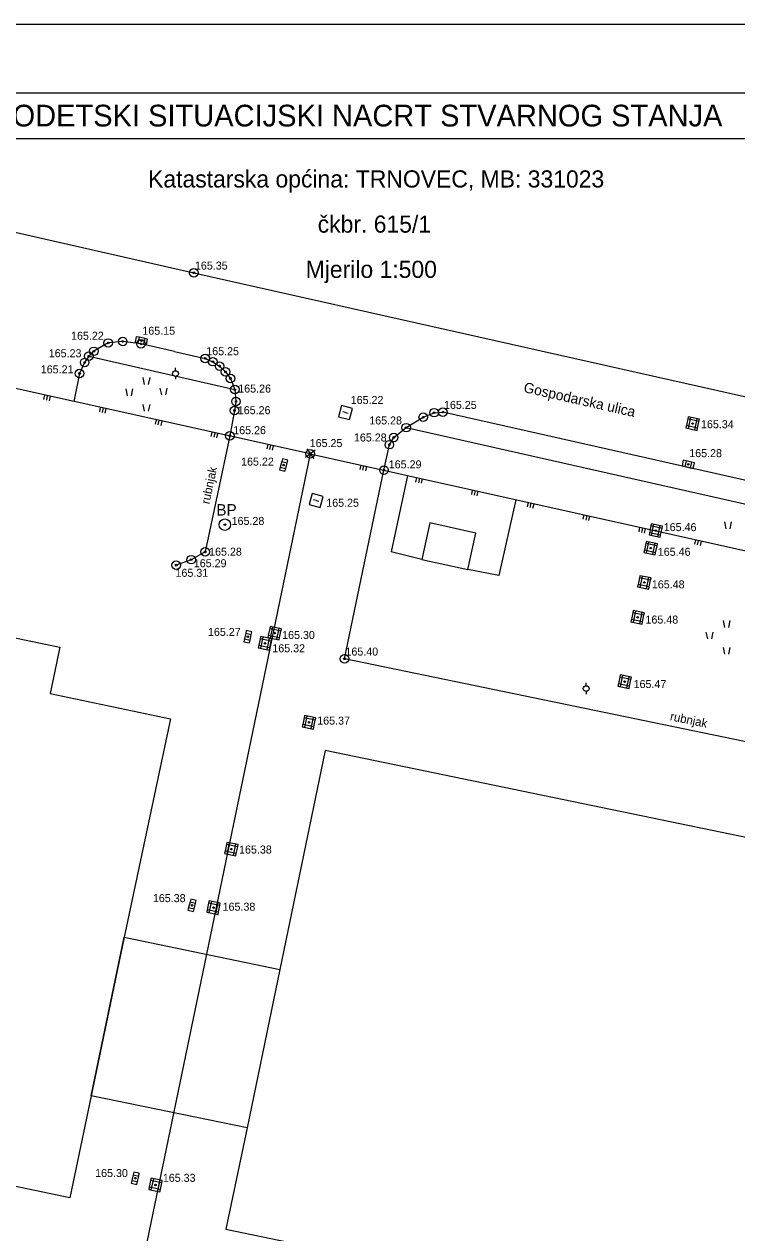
# Model space of a CAD drawing. Extents: x 492698 to 492905, y 5129124 to 5129334.
# Drawn here: x 492792.6 to 492855, y 5129228 to 5129333.7 of the extents above; entities that cross this region are included whole.
import ezdxf

# ---------------------------------------------------------------- set-up
doc = ezdxf.new("R2010")
doc.units = 0
for name, color, linetype in [('DETALJNE TOČKE', 7, 'Continuous'), ('KUĆNI BROJ', 7, 'Continuous'), ('MEĐA - stara', 7, 'Continuous'), ('MEĐAŠI', 7, 'Continuous'), ('NAZIVI POSJEDNIKA', 7, 'Continuous'), ('OBJEKTI - novi', 7, 'Continuous'), ('OBJEKTI - stari', 7, 'Continuous'), ('OBRAZCI', 7, 'Continuous'), ('TOPO - Znakovi', 7, 'Continuous'), ('VISINE', 7, 'Continuous')]:
    doc.layers.add(name, color=color, linetype=linetype)

msp = doc.modelspace()

# ---------------------------------------------------------------- linework, layer by layer
at = {"layer": 'MEĐA - stara'}
for p, q in [((492762.85, 5129322.07), (492807.48, 5129311.96)), ((492807.48, 5129311.96), (492891.56, 5129293.06)), ((492817.66, 5129296.12), (492756.96, 5129309.58)), ((492799.98, 5129305.82), (492798.72, 5129305.09)), ((492801.25, 5129305.95), (492799.98, 5129305.82)), ((492802.85, 5129305.74), (492801.25, 5129305.95)), ((492805.79, 5129305.06), (492802.85, 5129305.74)), ((492797.92, 5129304.1), (492797.47, 5129303.15)), ((492798.29, 5129304.66), (492797.92, 5129304.1)), ((492798.72, 5129305.09), (492798.29, 5129304.66)), ((492798.29, 5129304.66), (492811.06, 5129301.74)), ((492805.79, 5129305.06), (492808.47, 5129304.47)), ((492808.47, 5129304.47), (492809.14, 5129304.18)), ((492809.14, 5129304.18), (492809.73, 5129303.79)), ((492797.47, 5129303.15), (492796.97, 5129300.71)), ((492809.73, 5129303.79), (492810.25, 5129303.29)), ((492810.25, 5129303.29), (492810.68, 5129302.71)), ((492803.01, 5129302.8), (492803.13, 5129302.2)), ((492803.61, 5129302.8), (492803.48, 5129302.2)), ((492810.68, 5129302.71), (492811.06, 5129301.74)), ((492801.51, 5129301.8), (492801.63, 5129301.2)), ((492802.11, 5129301.8), (492801.98, 5129301.2)), ((492804.51, 5129301.87), (492804.63, 5129301.27)), ((492805.11, 5129301.87), (492804.98, 5129301.27)), ((492811.06, 5129301.74), (492811.16, 5129300.7)), ((492803.01, 5129300.45), (492803.13, 5129299.85)), ((492803.61, 5129300.45), (492803.48, 5129299.85)), ((492811.04, 5129299.91), (492810.62, 5129297.7)), ((492811.16, 5129300.7), (492811.04, 5129299.91)), ((492826.05, 5129298.41), (492827.55, 5129299.32)), ((492827.55, 5129299.32), (492828.5, 5129299.72)), ((492828.5, 5129299.72), (492829.27, 5129299.77)), ((492873.79, 5129289.71), (492829.27, 5129299.77)), ((492824.96, 5129297.55), (492826.05, 5129298.41)), ((492826.05, 5129298.41), (492875.78, 5129287.23)), ((492810.62, 5129297.7), (492808.47, 5129287.54)), ((492824.11, 5129294.7), (492824.58, 5129296.92)), ((492824.58, 5129296.92), (492824.96, 5129297.55)), ((492817.66, 5129296.12), (492788.55, 5129155.62)), ((492817.66, 5129296.12), (492882.48, 5129281.67)), ((492820.65, 5129278.19), (492824.11, 5129294.7)), ((492826.18, 5129294.22), (492824.75, 5129287.55)), ((492835.65, 5129292.11), (492834.15, 5129285.48)), ((492853.9, 5129290.17), (492854.03, 5129289.57)), ((492854.5, 5129290.17), (492854.38, 5129289.57)), ((492808.47, 5129287.54), (492807.24, 5129286.86)), ((492827.43, 5129286.89), (492824.75, 5129287.55)), ((492807.24, 5129286.86), (492805.93, 5129286.38)), ((492834.15, 5129285.48), (492831.44, 5129286)), ((492853.78, 5129281.53), (492853.91, 5129280.93)), ((492854.38, 5129281.53), (492854.26, 5129280.93)), ((492852.28, 5129280.53), (492852.41, 5129279.93)), ((492852.88, 5129280.53), (492852.76, 5129279.93)), ((492853.78, 5129279.18), (492853.91, 5129278.58)), ((492854.38, 5129279.18), (492854.26, 5129278.58)), ((492872.52, 5129267.46), (492820.65, 5129278.19))]:
    msp.add_line(p, q, dxfattribs=at)
at = {"layer": 'MEĐAŠI'}
for p, q in [((492818.09, 5129296.43), (492817.23, 5129295.81)), ((492817.35, 5129296.55), (492817.97, 5129295.69))]:
    msp.add_line(p, q, dxfattribs=at)
for centre, radius in [((492807.48, 5129311.96), 0.375), ((492807.48, 5129311.96), 0.075), ((492799.98, 5129305.82), 0.375), ((492801.25, 5129305.95), 0.375), ((492798.72, 5129305.09), 0.375), ((492798.72, 5129305.09), 0.075), ((492799.98, 5129305.82), 0.075), ((492801.25, 5129305.95), 0.075), ((492802.85, 5129305.74), 0.375), ((492802.85, 5129305.74), 0.075), ((492797.92, 5129304.1), 0.375), ((492797.92, 5129304.1), 0.075), ((492798.29, 5129304.66), 0.375), ((492798.29, 5129304.66), 0.075), ((492808.47, 5129304.47), 0.375), ((492808.47, 5129304.47), 0.075), ((492809.14, 5129304.18), 0.375), ((492809.14, 5129304.18), 0.075), ((492809.73, 5129303.79), 0.375), ((492797.47, 5129303.15), 0.375), ((492797.47, 5129303.15), 0.075), ((492809.73, 5129303.79), 0.075), ((492810.25, 5129303.29), 0.375), ((492810.25, 5129303.29), 0.075), ((492810.68, 5129302.71), 0.375), ((492810.68, 5129302.71), 0.075), ((492811.06, 5129301.74), 0.375), ((492811.16, 5129300.7), 0.375), ((492811.06, 5129301.74), 0.075), ((492811.04, 5129299.91), 0.375), ((492811.04, 5129299.91), 0.075), ((492811.16, 5129300.7), 0.075), ((492828.5, 5129299.72), 0.375), ((492829.27, 5129299.77), 0.375), ((492829.27, 5129299.77), 0.075), ((492826.05, 5129298.41), 0.375), ((492827.55, 5129299.32), 0.375), ((492827.55, 5129299.32), 0.075), ((492828.5, 5129299.72), 0.075), ((492810.62, 5129297.7), 0.375), ((492810.62, 5129297.7), 0.075), ((492824.96, 5129297.55), 0.375), ((492826.05, 5129298.41), 0.075), ((492824.58, 5129296.92), 0.375), ((492824.58, 5129296.92), 0.075), ((492824.96, 5129297.55), 0.075), ((492817.66, 5129296.12), 0.075), ((492824.11, 5129294.7), 0.375), ((492824.11, 5129294.7), 0.075), ((492807.24, 5129286.86), 0.375), ((492808.47, 5129287.54), 0.375), ((492808.47, 5129287.54), 0.075), ((492805.93, 5129286.38), 0.375), ((492805.93, 5129286.38), 0.075), ((492807.24, 5129286.86), 0.075), ((492820.65, 5129278.19), 0.375), ((492820.65, 5129278.19), 0.075)]:
    msp.add_circle(centre, radius, dxfattribs=at)
for start, end in [(170.9579, 350.9579), (350.9579, 170.9579)]:
    msp.add_arc((492817.66, 5129296.12), 0.075, start, end, dxfattribs=at)
at = {"layer": 'OBJEKTI - novi'}
msp.add_circle((492817.66, 5129296.12), 0.375, dxfattribs=at)
at = {"layer": 'OBJEKTI - stari'}
for points in [[(492828.11, 5129290.08), (492827.43, 5129286.89), (492831.44, 5129286), (492832.15, 5129289.18)], [(492805.42, 5129272.95), (492801.38, 5129253.83), (492798.48, 5129239.95), (492796.63, 5129231.02), (492786.16, 5129233.21), (492785.3, 5129229.11), (492772.8, 5129231.7), (492773.65, 5129235.81), (492723.64, 5129246.23), (492732.34, 5129288.11), (492782.39, 5129277.73), (492783.23, 5129281.79), (492795.74, 5129279.2), (492794.89, 5129275.14)], [(492818.96, 5129270.18), (492815.01, 5129251.01), (492812.14, 5129237.15), (492810.27, 5129228.29), (492862.15, 5129217.52), (492870.87, 5129259.44)], [(492801.38, 5129253.83), (492815.01, 5129251.01), (492812.14, 5129237.15), (492798.48, 5129239.95)]]:
    msp.add_lwpolyline(points, close=True, dxfattribs=at)
at = {"layer": 'OBRAZCI'}
for p, q in [((492748.91, 5129333.71), (492897.41, 5129333.71)), ((492754.91, 5129327.71), (492891.41, 5129327.71)), ((492754.91, 5129327.71), (492847.91, 5129327.71)), ((492754.91, 5129327.71), (492847.91, 5129327.71)), ((492754.91, 5129327.71), (492847.91, 5129327.71)), ((492754.91, 5129327.71), (492847.91, 5129327.71)), ((492754.91, 5129323.71), (492891.41, 5129323.71))]:
    msp.add_line(p, q, dxfattribs=at)
at = {"layer": 'TOPO - Znakovi'}
for p, q in [((492802.44, 5129306.37), (492802.34, 5129305.88)), ((492802.69, 5129306.32), (492802.44, 5129306.37)), ((492802.69, 5129306.32), (492802.58, 5129305.83)), ((492803.18, 5129306.21), (492802.69, 5129306.32)), ((492803.18, 5129306.21), (492803.07, 5129305.72)), ((492803.42, 5129306.16), (492803.18, 5129306.21)), ((492802.34, 5129305.88), (492802.58, 5129305.83)), ((492802.58, 5129305.83), (492803.07, 5129305.72)), ((492803.07, 5129305.72), (492803.32, 5129305.67)), ((492803.32, 5129305.67), (492803.42, 5129306.16)), ((492805.87, 5129303.39), (492805.87, 5129303.64)), ((492805.87, 5129302.89), (492805.87, 5129302.64)), ((492794.35, 5129300.88), (492794.44, 5129301.27)), ((492794.6, 5129300.82), (492794.68, 5129301.21)), ((492794.84, 5129300.77), (492794.93, 5129301.16)), ((492799.24, 5129299.8), (492799.32, 5129300.19)), ((492799.48, 5129299.74), (492799.57, 5129300.13)), ((492799.72, 5129299.69), (492799.81, 5129300.08)), ((492820.38, 5129300.34), (492820.13, 5129299.37)), ((492821.35, 5129300.09), (492820.38, 5129300.34)), ((492821.1, 5129299.12), (492821.35, 5129300.09)), ((492804.12, 5129298.71), (492804.2, 5129299.1)), ((492804.36, 5129298.66), (492804.45, 5129299.05)), ((492804.61, 5129298.61), (492804.69, 5129299)), ((492820.13, 5129299.37), (492821.1, 5129299.12)), ((492820.74, 5129299.73), (492820.5, 5129299.79)), ((492820.74, 5129299.73), (492820.98, 5129299.67)), ((492850.7, 5129299.17), (492850.57, 5129298.59)), ((492850.74, 5129299.37), (492850.7, 5129299.17)), ((492851.67, 5129298.95), (492850.7, 5129299.17)), ((492850.94, 5129299.32), (492850.72, 5129298.35)), ((492851.72, 5129299.15), (492850.74, 5129299.37)), ((492851.3, 5129298.22), (492851.52, 5129299.19)), ((492851.54, 5129298.37), (492851.67, 5129298.95)), ((492851.67, 5129298.95), (492851.72, 5129299.15)), ((492809, 5129297.63), (492809.09, 5129298.02)), ((492809.24, 5129297.58), (492809.33, 5129297.97)), ((492809.49, 5129297.52), (492809.57, 5129297.91)), ((492850.57, 5129298.59), (492850.52, 5129298.39)), ((492850.52, 5129298.39), (492851.5, 5129298.17)), ((492851.54, 5129298.37), (492850.57, 5129298.59)), ((492851.5, 5129298.17), (492851.54, 5129298.37)), ((492813.88, 5129296.55), (492813.97, 5129296.94)), ((492814.12, 5129296.49), (492814.21, 5129296.88)), ((492814.37, 5129296.44), (492814.45, 5129296.83)), ((492815.23, 5129295.69), (492815.16, 5129295.45)), ((492815.71, 5129295.56), (492815.23, 5129295.69)), ((492815.03, 5129294.96), (492814.97, 5129294.72)), ((492814.97, 5129294.72), (492815.45, 5129294.59)), ((492815.16, 5129295.45), (492815.03, 5129294.96)), ((492815.03, 5129294.96), (492815.52, 5129294.83)), ((492815.16, 5129295.45), (492815.65, 5129295.32)), ((492815.45, 5129294.59), (492815.52, 5129294.83)), ((492815.52, 5129294.83), (492815.65, 5129295.32)), ((492815.65, 5129295.32), (492815.71, 5129295.56)), ((492822.03, 5129294.74), (492822.11, 5129295.13)), ((492822.27, 5129294.68), (492822.36, 5129295.07)), ((492822.51, 5129294.63), (492822.6, 5129295.02)), ((492850.3, 5129295.56), (492850.19, 5129295.08)), ((492850.19, 5129295.08), (492850.43, 5129295.02)), ((492850.55, 5129295.5), (492850.3, 5129295.56)), ((492850.55, 5129295.5), (492850.43, 5129295.02)), ((492850.43, 5129295.02), (492850.91, 5129294.9)), ((492851.03, 5129295.38), (492850.55, 5129295.5)), ((492851.03, 5129295.38), (492850.91, 5129294.9)), ((492850.91, 5129294.9), (492851.16, 5129294.84)), ((492851.27, 5129295.32), (492851.03, 5129295.38)), ((492851.16, 5129294.84), (492851.27, 5129295.32)), ((492826.91, 5129293.65), (492826.99, 5129294.04)), ((492827.15, 5129293.59), (492827.24, 5129293.99)), ((492827.39, 5129293.54), (492827.48, 5129293.93)), ((492817.82, 5129292.65), (492817.57, 5129291.68)), ((492818.79, 5129292.4), (492817.82, 5129292.65)), ((492831.79, 5129292.56), (492831.87, 5129292.95)), ((492832.03, 5129292.51), (492832.12, 5129292.9)), ((492832.27, 5129292.45), (492832.36, 5129292.84)), ((492817.57, 5129291.68), (492818.54, 5129291.43)), ((492818.18, 5129292.04), (492817.94, 5129292.1)), ((492818.18, 5129292.04), (492818.42, 5129291.98)), ((492818.54, 5129291.43), (492818.79, 5129292.4)), ((492836.67, 5129291.47), (492836.75, 5129291.86)), ((492836.91, 5129291.42), (492837, 5129291.81)), ((492837.15, 5129291.36), (492837.24, 5129291.75)), ((492841.55, 5129290.39), (492841.63, 5129290.78)), ((492841.79, 5129290.33), (492841.88, 5129290.72)), ((492842.03, 5129290.28), (492842.12, 5129290.67)), ((492846.43, 5129289.3), (492846.51, 5129289.69)), ((492846.67, 5129289.24), (492846.76, 5129289.63)), ((492846.91, 5129289.19), (492847, 5129289.58)), ((492847.46, 5129289.81), (492847.34, 5129289.22)), ((492847.5, 5129290), (492847.46, 5129289.81)), ((492848.44, 5129289.6), (492847.46, 5129289.81)), ((492847.7, 5129289.96), (492847.49, 5129288.98)), ((492848.48, 5129289.8), (492847.5, 5129290)), ((492848.08, 5129288.86), (492848.29, 5129289.84)), ((492848.32, 5129289.01), (492848.44, 5129289.6)), ((492848.44, 5129289.6), (492848.48, 5129289.8)), ((492847.02, 5129288.27), (492846.9, 5129287.68)), ((492847.06, 5129288.46), (492847.02, 5129288.27)), ((492848, 5129288.06), (492847.02, 5129288.27)), ((492847.26, 5129288.42), (492847.05, 5129287.44)), ((492848.04, 5129288.26), (492847.06, 5129288.46)), ((492847.34, 5129289.22), (492847.3, 5129289.02)), ((492847.3, 5129289.02), (492848.28, 5129288.82)), ((492848.32, 5129289.01), (492847.34, 5129289.22)), ((492847.64, 5129287.32), (492847.85, 5129288.3)), ((492848, 5129288.06), (492848.04, 5129288.26)), ((492848.28, 5129288.82), (492848.32, 5129289.01)), ((492851.31, 5129288.21), (492851.39, 5129288.6)), ((492851.55, 5129288.16), (492851.64, 5129288.55)), ((492851.8, 5129288.1), (492851.88, 5129288.49)), ((492846.9, 5129287.68), (492846.86, 5129287.48)), ((492846.86, 5129287.48), (492847.84, 5129287.28)), ((492847.88, 5129287.47), (492846.9, 5129287.68)), ((492847.84, 5129287.28), (492847.88, 5129287.47)), ((492847.88, 5129287.47), (492848, 5129288.06)), ((492846.46, 5129285.27), (492846.34, 5129284.68)), ((492846.5, 5129285.46), (492846.46, 5129285.27)), ((492847.44, 5129285.06), (492846.46, 5129285.27)), ((492846.7, 5129285.42), (492846.49, 5129284.44)), ((492847.48, 5129285.26), (492846.5, 5129285.46)), ((492847.08, 5129284.32), (492847.29, 5129285.3)), ((492847.32, 5129284.47), (492847.44, 5129285.06)), ((492847.44, 5129285.06), (492847.48, 5129285.26)), ((492846.34, 5129284.68), (492846.3, 5129284.48)), ((492846.3, 5129284.48), (492847.28, 5129284.28)), ((492847.32, 5129284.47), (492846.34, 5129284.68)), ((492847.28, 5129284.28), (492847.32, 5129284.47)), ((492845.88, 5129282.21), (492845.76, 5129281.62)), ((492845.92, 5129282.4), (492845.88, 5129282.21)), ((492846.86, 5129282), (492845.88, 5129282.21)), ((492846.12, 5129282.36), (492845.91, 5129281.38)), ((492846.9, 5129282.2), (492845.92, 5129282.4)), ((492846.5, 5129281.26), (492846.71, 5129282.24)), ((492846.74, 5129281.41), (492846.86, 5129282)), ((492846.86, 5129282), (492846.9, 5129282.2)), ((492814.11, 5129280.83), (492813.99, 5129280.24)), ((492814.15, 5129281.02), (492814.11, 5129280.83)), ((492815.09, 5129280.62), (492814.11, 5129280.83)), ((492814.35, 5129280.98), (492814.14, 5129280)), ((492815.13, 5129280.82), (492814.15, 5129281.02)), ((492814.73, 5129279.88), (492814.94, 5129280.86)), ((492815.09, 5129280.62), (492815.13, 5129280.82)), ((492845.76, 5129281.62), (492845.72, 5129281.42)), ((492845.72, 5129281.42), (492846.7, 5129281.22)), ((492846.74, 5129281.41), (492845.76, 5129281.62)), ((492846.7, 5129281.22), (492846.74, 5129281.41)), ((492811.9, 5129279.93), (492811.85, 5129279.68)), ((492812.01, 5129280.42), (492811.9, 5129279.93)), ((492811.9, 5129279.93), (492812.39, 5129279.82)), ((492812.06, 5129280.66), (492812.01, 5129280.42)), ((492812.01, 5129280.42), (492812.5, 5129280.31)), ((492812.55, 5129280.56), (492812.06, 5129280.66)), ((492812.34, 5129279.58), (492812.39, 5129279.82)), ((492812.39, 5129279.82), (492812.5, 5129280.31)), ((492812.5, 5129280.31), (492812.55, 5129280.56)), ((492813.27, 5129279.94), (492813.15, 5129279.35)), ((492813.31, 5129280.13), (492813.27, 5129279.94)), ((492814.25, 5129279.73), (492813.27, 5129279.94)), ((492813.51, 5129280.09), (492813.3, 5129279.11)), ((492814.29, 5129279.93), (492813.31, 5129280.13)), ((492813.89, 5129278.99), (492814.1, 5129279.97)), ((492813.99, 5129280.24), (492813.95, 5129280.04)), ((492813.95, 5129280.04), (492814.93, 5129279.84)), ((492814.97, 5129280.03), (492813.99, 5129280.24)), ((492814.25, 5129279.73), (492814.29, 5129279.93)), ((492814.93, 5129279.84), (492814.97, 5129280.03)), ((492814.97, 5129280.03), (492815.09, 5129280.62)), ((492811.85, 5129279.68), (492812.34, 5129279.58)), ((492813.15, 5129279.35), (492813.11, 5129279.15)), ((492813.11, 5129279.15), (492814.09, 5129278.95)), ((492814.13, 5129279.14), (492813.15, 5129279.35)), ((492814.09, 5129278.95), (492814.13, 5129279.14)), ((492814.13, 5129279.14), (492814.25, 5129279.73)), ((492844.74, 5129276.59), (492844.62, 5129276)), ((492844.78, 5129276.78), (492844.74, 5129276.59)), ((492845.72, 5129276.38), (492844.74, 5129276.59)), ((492844.98, 5129276.74), (492844.77, 5129275.76)), ((492845.76, 5129276.58), (492844.78, 5129276.78)), ((492845.36, 5129275.64), (492845.57, 5129276.62)), ((492845.72, 5129276.38), (492845.76, 5129276.58)), ((492841.8, 5129275.83), (492841.8, 5129276.08)), ((492844.62, 5129276), (492844.58, 5129275.8)), ((492844.58, 5129275.8), (492845.56, 5129275.6)), ((492845.6, 5129275.79), (492844.62, 5129276)), ((492845.56, 5129275.6), (492845.6, 5129275.79)), ((492845.6, 5129275.79), (492845.72, 5129276.38)), ((492841.8, 5129275.33), (492841.8, 5129275.08)), ((492817, 5129272.44), (492816.96, 5129272.24)), ((492817.12, 5129273.03), (492817, 5129272.44)), ((492817.98, 5129272.23), (492817, 5129272.44)), ((492817.16, 5129273.22), (492817.12, 5129273.03)), ((492818.1, 5129272.82), (492817.12, 5129273.03)), ((492817.36, 5129273.18), (492817.15, 5129272.2)), ((492818.14, 5129273.02), (492817.16, 5129273.22)), ((492817.74, 5129272.08), (492817.95, 5129273.06)), ((492817.98, 5129272.23), (492818.1, 5129272.82)), ((492818.1, 5129272.82), (492818.14, 5129273.02)), ((492816.96, 5129272.24), (492817.94, 5129272.04)), ((492817.94, 5129272.04), (492817.98, 5129272.23)), ((492810.33, 5129261.94), (492810.21, 5129261.35)), ((492810.37, 5129262.13), (492810.33, 5129261.94)), ((492811.31, 5129261.73), (492810.33, 5129261.94)), ((492810.57, 5129262.09), (492810.36, 5129261.11)), ((492811.35, 5129261.93), (492810.37, 5129262.13)), ((492810.95, 5129260.99), (492811.16, 5129261.97)), ((492811.31, 5129261.73), (492811.35, 5129261.93)), ((492810.21, 5129261.35), (492810.17, 5129261.15)), ((492810.17, 5129261.15), (492811.15, 5129260.95)), ((492811.19, 5129261.14), (492810.21, 5129261.35)), ((492811.15, 5129260.95), (492811.19, 5129261.14)), ((492811.19, 5129261.14), (492811.31, 5129261.73)), ((492807.14, 5129256.92), (492807.02, 5129256.44)), ((492807.2, 5129257.17), (492807.14, 5129256.92)), ((492807.14, 5129256.92), (492807.62, 5129256.8)), ((492807.69, 5129257.04), (492807.2, 5129257.17)), ((492807.5, 5129256.32), (492807.62, 5129256.8)), ((492807.62, 5129256.8), (492807.69, 5129257.04)), ((492808.77, 5129256.82), (492808.65, 5129256.23)), ((492808.81, 5129257.01), (492808.77, 5129256.82)), ((492809.75, 5129256.61), (492808.77, 5129256.82)), ((492809.01, 5129256.97), (492808.8, 5129255.99)), ((492809.79, 5129256.81), (492808.81, 5129257.01)), ((492809.39, 5129255.87), (492809.6, 5129256.85)), ((492809.63, 5129256.02), (492809.75, 5129256.61)), ((492809.75, 5129256.61), (492809.79, 5129256.81)), ((492807.02, 5129256.44), (492806.95, 5129256.2)), ((492806.95, 5129256.2), (492807.44, 5129256.07)), ((492807.02, 5129256.44), (492807.5, 5129256.32)), ((492807.44, 5129256.07), (492807.5, 5129256.32)), ((492808.65, 5129256.23), (492808.61, 5129256.03)), ((492808.61, 5129256.03), (492809.59, 5129255.83)), ((492809.63, 5129256.02), (492808.65, 5129256.23)), ((492809.59, 5129255.83), (492809.63, 5129256.02)), ((492802.21, 5129233.29), (492802.16, 5129233.05)), ((492802.7, 5129233.19), (492802.21, 5129233.29)), ((492802.05, 5129232.56), (492802, 5129232.31)), ((492802, 5129232.31), (492802.49, 5129232.21)), ((492802.16, 5129233.05), (492802.05, 5129232.56)), ((492802.05, 5129232.56), (492802.54, 5129232.45)), ((492802.16, 5129233.05), (492802.65, 5129232.94)), ((492802.49, 5129232.21), (492802.54, 5129232.45)), ((492802.54, 5129232.45), (492802.65, 5129232.94)), ((492802.65, 5129232.94), (492802.7, 5129233.19)), ((492803.69, 5129232.55), (492803.57, 5129231.96)), ((492803.73, 5129232.74), (492803.69, 5129232.55)), ((492804.67, 5129232.34), (492803.69, 5129232.55)), ((492803.93, 5129232.7), (492803.72, 5129231.72)), ((492804.71, 5129232.54), (492803.73, 5129232.74)), ((492804.31, 5129231.6), (492804.52, 5129232.58)), ((492804.55, 5129231.75), (492804.67, 5129232.34)), ((492804.67, 5129232.34), (492804.71, 5129232.54)), ((492803.57, 5129231.96), (492803.53, 5129231.76)), ((492803.53, 5129231.76), (492804.51, 5129231.56)), ((492804.55, 5129231.75), (492803.57, 5129231.96)), ((492804.51, 5129231.56), (492804.55, 5129231.75))]:
    msp.add_line(p, q, dxfattribs=at)
for centre, radius in [((492802.88, 5129306.02), 0.065), ((492805.87, 5129303.14), 0.25), ((492851.12, 5129298.77), 0.065), ((492815.34, 5129295.14), 0.065), ((492850.73, 5129295.2), 0.065), ((492810.19, 5129289.92), 0.5), ((492810.19, 5129289.92), 0.075), ((492847.89, 5129289.41), 0.065), ((492847.45, 5129287.87), 0.065), ((492846.89, 5129284.87), 0.065), ((492846.31, 5129281.81), 0.065), ((492812.2, 5129280.12), 0.065), ((492814.54, 5129280.43), 0.065), ((492813.7, 5129279.54), 0.065), ((492841.8, 5129275.58), 0.25), ((492845.17, 5129276.19), 0.065), ((492817.55, 5129272.63), 0.065), ((492810.76, 5129261.54), 0.065), ((492807.32, 5129256.62), 0.065), ((492809.2, 5129256.42), 0.065), ((492802.35, 5129232.75), 0.065), ((492804.12, 5129232.15), 0.065)]:
    msp.add_circle(centre, radius, dxfattribs=at)

# ---------------------------------------------------------------- texts
at = {"layer": 'DETALJNE TOČKE'}
msp.add_text('BP', height=1, dxfattribs=at).set_placement((492809.44, 5129290.72))
at = {"layer": 'KUĆNI BROJ'}
for rotation, p in [(78.0517, (492808.83, 5129291.68)), (348.3125, (492849.1, 5129272.82))]:
    msp.add_text('rubnjak', height=0.75, rotation=rotation, dxfattribs=at).set_placement(p)
at = {"layer": 'NAZIVI POSJEDNIKA'}
msp.add_text('Gospodarska ulica', height=0.9, rotation=347.267, dxfattribs=at).set_placement((492836.27, 5129301.53))
at = {"layer": 'OBRAZCI'}
for s, height, p in [('GEODETSKI SITUACIJSKI NACRT STVARNOG STANJA', 1.9, (492787.94, 5129324.76)), ('Katastarska općina: TRNOVEC, MB: 331023', 1.5, (492803.47, 5129319.42)), ('čkbr. 615/1', 1.5, (492818.31, 5129315.47)), ('Mjerilo 1:500', 1.5, (492817.26, 5129311.51))]:
    msp.add_text(s, height=height, dxfattribs=at).set_placement(p)
at = {"layer": 'VISINE'}
for s, p in [('165.35', (492807.57, 5129312.24)), ('165.15', (492802.97, 5129306.54)), ('165.22', (492796.73, 5129306.1)), ('165.23', (492794.78, 5129304.57)), ('165.25', (492808.56, 5129304.75)), ('165.21', (492794.08, 5129303.16)), ('165.26', (492811.36, 5129301.48)), ('165.22', (492821.2, 5129300.48)), ('165.26', (492811.32, 5129299.59)), ('165.25', (492829.36, 5129300.05)), ('165.28', (492822.82, 5129298.69)), ('165.34', (492851.85, 5129298.36)), ('165.26', (492810.92, 5129297.84)), ('165.28', (492821.48, 5129297.2)), ('165.25', (492817.61, 5129296.71)), ('165.22', (492811.61, 5129295.09)), ('165.28', (492850.82, 5129295.83)), ('165.29', (492824.53, 5129294.85)), ('165.25', (492819.06, 5129291.49)), ('165.28', (492810.78, 5129289.9)), ('165.46', (492848.59, 5129289.36)), ('165.28', (492808.81, 5129287.21)), ('165.46', (492848.07, 5129287.2)), ('165.29', (492807.47, 5129286.2)), ('165.31', (492805.87, 5129285.36)), ('165.48', (492847.55, 5129284.35)), ('165.48', (492846.99, 5129281.27)), ('165.27', (492808.71, 5129280.19)), ('165.30', (492815.2, 5129279.92)), ('165.32', (492814.34, 5129278.76)), ('165.40', (492820.74, 5129278.47)), ('165.47', (492845.95, 5129275.63)), ('165.37', (492818.27, 5129272.43)), ('165.38', (492811.43, 5129261.15)), ('165.38', (492803.89, 5129256.9)), ('165.38', (492809.99, 5129256.15)), ('165.30', (492798.84, 5129232.85)), ('165.33', (492804.76, 5129232.43))]:
    msp.add_text(s, height=0.7, dxfattribs=at).set_placement(p)

doc.saveas('drawing.dxf')
